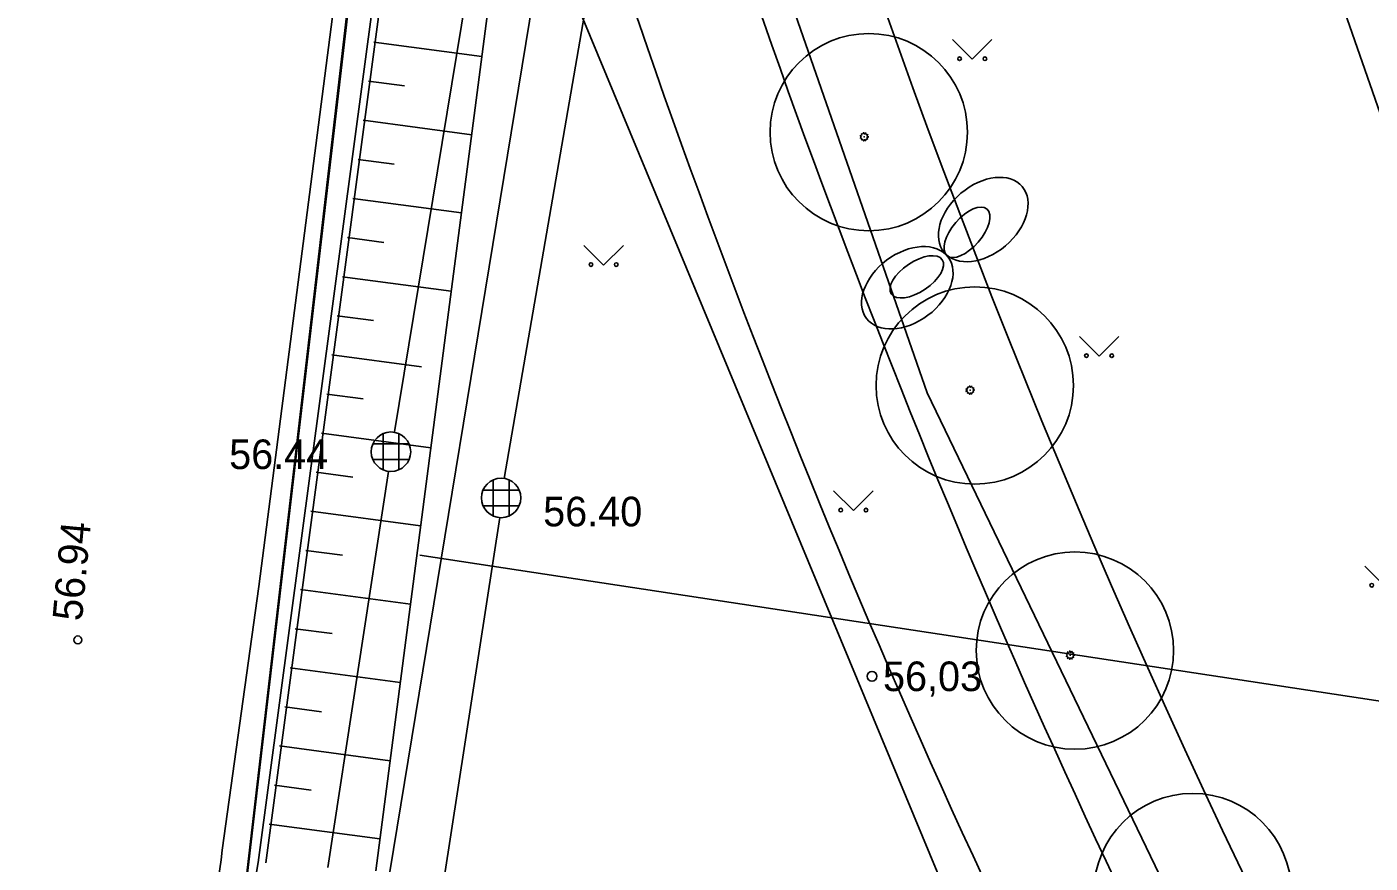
# Model space of a CAD drawing. Extents: x 9156 to 9809, y 2728 to 4000.
# Drawn here: x 9410.12 to 9444.15, y 3825.13 to 3846.32 of the extents above; entities that cross this region are included whole.
import ezdxf

# ---------------------------------------------------------------- set-up
doc = ezdxf.new("R2010")
doc.units = 0
for name, color, linetype in [('Level 12', 7, 'Continuous'), ('Level 14', 7, 'Continuous'), ('Level 17', 7, 'Continuous'), ('Level 18', 7, 'Continuous'), ('Level 41', 7, 'Continuous'), ('Level 54', 7, 'Continuous'), ('Level 56', 7, 'Continuous'), ('Level 6', 7, 'Continuous'), ('Level 7', 7, 'Continuous'), ('Level 8', 7, 'Continuous'), ('Level 9', 7, 'Continuous')]:
    doc.layers.add(name, color=color, linetype=linetype)

# ---------------------------------------------------------------- blocks, each defined once
blk = doc.blocks.new('MURU')
at = {"layer": 'Level 41'}
for p, q in [((-0.5, 0.5), (0, 0)), ((0, 0), (0.5, 0.5))]:
    blk.add_line(p, q, dxfattribs=at)
for centre in [(-0.32, 0.015), (0.32, 0.014)]:
    blk.add_circle(centre, 0.0466, dxfattribs=at)

msp = doc.modelspace()

# ---------------------------------------------------------------- linework, layer by layer
at = {"layer": 'Level 12'}
for p, q in [((9432.928, 3837.052), (9429.455, 3847.022)), ((9440.781, 3820.735), (9432.928, 3837.052))]:
    msp.add_line(p, q, dxfattribs=at)
at = {"layer": 'Level 14'}
msp.add_line((9444.967, 3842.49), (9431.28, 3881.958), dxfattribs=at)
at = {"layer": 'Level 17'}
for centre, radius, start, end in [((9631.829, 3934.713), 192.9, 187.13653, 212.29226), ((9631.829, 3934.713), 195.9, 187.89598, 211.0202), ((9639.344, 3919.894), 226, 185.96508, 207.05054), ((9639.344, 3919.894), 223, 186.63117, 207.05059)]:
    msp.add_arc(centre, radius, start, end, dxfattribs=at)
at = {"layer": 'Level 18'}
for centre, radius, start, end in [((9631.829, 3934.713), 198.9, 190.27283, 207.99609), ((9639.344, 3919.894), 220, 188.1609, 207.05049)]:
    msp.add_arc(centre, radius, start, end, dxfattribs=at)
at = {"layer": 'Level 54'}
for p, q in [((9428.052, 3915.601), (9415.976, 3825.147)), ((9427.378, 3909.376), (9416.171, 3825.133)), ((9419.432, 3836.064), (9425.772, 3874.586)), ((9429.001, 3874.205), (9422.209, 3834.878)), ((9418.905, 3845.939), (9421.645, 3845.573)), ((9418.773, 3844.948), (9419.687, 3844.826)), ((9418.64, 3843.957), (9421.387, 3843.59)), ((9418.508, 3842.966), (9419.424, 3842.843)), ((9418.375, 3841.974), (9421.128, 3841.607)), ((9418.243, 3840.983), (9419.162, 3840.861)), ((9418.111, 3839.992), (9420.87, 3839.623)), ((9417.978, 3839.001), (9418.899, 3838.878)), ((9420.75, 3838.705), (9418.955, 3824.932)), ((9417.846, 3838.01), (9420.113, 3837.707)), ((9417.713, 3837.018), (9418.636, 3836.895)), ((9417.581, 3836.027), (9420.353, 3835.657)), ((9418.884, 3835.756), (9419.8, 3835.756)), ((9419.142, 3836.014), (9419.142, 3835.098)), ((9419.542, 3836.014), (9419.542, 3835.098)), ((9417.449, 3835.036), (9418.374, 3834.912)), ((9417.739, 3825.02), (9419.277, 3835.055)), ((9418.884, 3835.356), (9419.8, 3835.356)), ((9421.932, 3834.842), (9421.932, 3833.926)), ((9422.332, 3834.842), (9422.332, 3833.926)), ((9421.674, 3834.584), (9422.59, 3834.584)), ((9417.316, 3834.045), (9420.094, 3833.674)), ((9421.674, 3834.184), (9422.59, 3834.184)), ((9420.7, 3824.806), (9422.096, 3833.885)), ((9417.184, 3833.054), (9418.111, 3832.93)), ((9417.051, 3832.062), (9419.836, 3831.691)), ((9416.919, 3831.071), (9417.848, 3830.947)), ((9416.787, 3830.08), (9419.577, 3829.707)), ((9416.654, 3829.089), (9417.585, 3828.964)), ((9416.522, 3828.098), (9419.318, 3827.724)), ((9416.389, 3827.106), (9417.323, 3826.982)), ((9416.257, 3826.115), (9419.06, 3825.741))]:
    msp.add_line(p, q, dxfattribs=at)
for points in [[(9415.997, 3832.136), (9418.853, 3854.304), (9418.853, 3854.304), (9418.027, 3862.261), (9417.976, 3870.031), (9426.142, 3917.687)], [(9419.311, 3824.906), (9430.024, 3890.161), (9433.2, 3889.656), (9434.423, 3896.884), (9431.507, 3897.561), (9431.927, 3902.125)], [(9428.218, 3901.358), (9428.633, 3899.185), (9420.75, 3838.705)], [(9520.273, 3827.766), (9490.843, 3825.804), (9472.66, 3826.338), (9457.151, 3826.873), (9448.238, 3828.654), (9420.073, 3832.93)], [(9415.037, 3825.215), (9415.063, 3825.456), (9415.997, 3832.136)], [(9430.118, 3737.47), (9419.84, 3752.661), (9416.921, 3758.115), (9414.288, 3763.295), (9411.358, 3770.89), (9409.441, 3780.316), (9410.66, 3795.64), (9415.037, 3825.215)]]:
    msp.add_lwpolyline(points, dxfattribs=at)
for centre, radius in [((9419.342, 3835.556), 0.5), ((9422.132, 3834.384), 0.5), ((9411.41, 3830.786), 0.1), ((9431.528, 3829.864), 0.125)]:
    msp.add_circle(centre, radius, dxfattribs=at)
msp.add_open_spline([(9415.976, 3825.147), (9415.093, 3819.866), (9413.578, 3808.546), (9411.641, 3794.709), (9410.924, 3784.763), (9411.76, 3776.853), (9413.792, 3771.101), (9417.009, 3763.374), (9419.226, 3759.393), (9422.553, 3753.458)], degree=3, dxfattribs=at)
at = {"layer": 'Level 56'}
for centre, radius, start, end in [((9631.829, 3934.713), 192.9, 187.13653, 212.29226), ((9631.829, 3934.713), 195.9, 187.89598, 211.0202), ((9631.829, 3934.713), 198.9, 190.27283, 207.99609), ((9639.344, 3919.894), 226, 185.96508, 207.05054), ((9639.344, 3919.894), 223, 186.63117, 207.05059), ((9639.344, 3919.894), 220, 188.1609, 207.05049)]:
    msp.add_arc(centre, radius, start, end, dxfattribs=at)
at = {"layer": 'Level 6'}
msp.add_lwpolyline([(9406.335, 3871.284), (9417.264, 3870.77), (9419.931, 3861.081), (9410.086, 3776.653), (9389.428, 3778.75), (9392.066, 3801.386), (9401.769, 3871.605)], close=True, dxfattribs=at)
msp.add_lwpolyline([(9397.586, 3777.922), (9410.086, 3776.653), (9418.608, 3850.018)], dxfattribs=at)
at = {"layer": 'Level 7'}
msp.add_line((9423.602, 3847.995), (9436.729, 3816.345), dxfattribs=at)
at = {"layer": 'Level 8'}
for centre, major_axis, ratio in [((9434.346, 3841.44), (-0.986, -0.837), 0.674652), ((9434.346, 3841.44), (-0.986, -0.837), 0.674652), ((9434.346, 3841.44), (-0.986, -0.837), 0.674652), ((9434.346, 3841.44), (-0.986, -0.837), 0.674652), ((9433.934, 3841.117), (-0.507, -0.589), 0.486914), ((9433.934, 3841.117), (-0.507, -0.589), 0.486914), ((9433.934, 3841.117), (-0.507, -0.589), 0.486914), ((9433.934, 3841.117), (-0.507, -0.589), 0.486914), ((9432.422, 3839.711), (1.034, 0.776), 0.674652), ((9432.422, 3839.711), (1.034, 0.776), 0.674652), ((9432.422, 3839.711), (1.034, 0.776), 0.674652), ((9432.422, 3839.711), (1.034, 0.776), 0.674652), ((9432.662, 3839.988), (0.646, 0.434), 0.486914), ((9432.662, 3839.988), (0.646, 0.434), 0.486914), ((9432.662, 3839.988), (0.646, 0.434), 0.486914), ((9432.662, 3839.988), (0.646, 0.434), 0.486914)]:
    msp.add_ellipse(centre, major_axis=major_axis, ratio=ratio, dxfattribs=at)
at = {"layer": 'Level 9'}
for p, q in [((9431.251, 3843.549), (9431.23, 3843.552)), ((9431.23, 3843.523), (9431.251, 3843.527)), ((9431.238, 3843.579), (9431.258, 3843.571)), ((9431.27, 3843.589), (9431.253, 3843.603)), ((9431.275, 3843.622), (9431.286, 3843.603)), ((9431.308, 3843.613), (9431.301, 3843.634)), ((9431.34, 3843.536), (9431.319, 3843.536)), ((9431.329, 3843.638), (9431.329, 3843.616)), ((9431.329, 3843.526), (9431.329, 3843.547)), ((9431.351, 3843.613), (9431.357, 3843.634)), ((9431.383, 3843.622), (9431.373, 3843.603)), ((9431.389, 3843.589), (9431.405, 3843.603)), ((9431.421, 3843.579), (9431.401, 3843.569)), ((9431.407, 3843.548), (9431.429, 3843.552)), ((9431.429, 3843.524), (9431.408, 3843.527)), ((9431.258, 3843.505), (9431.238, 3843.495)), ((9431.253, 3843.472), (9431.269, 3843.486)), ((9431.287, 3843.471), (9431.275, 3843.453)), ((9431.3, 3843.441), (9431.306, 3843.462)), ((9431.329, 3843.458), (9431.329, 3843.437)), ((9431.357, 3843.441), (9431.352, 3843.462)), ((9431.371, 3843.471), (9431.383, 3843.453)), ((9431.406, 3843.472), (9431.39, 3843.487)), ((9431.401, 3843.505), (9431.421, 3843.497)), ((9433.936, 3837.129), (9433.915, 3837.132)), ((9433.915, 3837.104), (9433.936, 3837.107)), ((9433.923, 3837.16), (9433.943, 3837.152)), ((9433.943, 3837.085), (9433.923, 3837.076)), ((9433.938, 3837.052), (9433.954, 3837.067)), ((9433.955, 3837.17), (9433.939, 3837.184)), ((9433.96, 3837.202), (9433.971, 3837.184)), ((9433.993, 3837.194), (9433.986, 3837.214)), ((9434.025, 3837.117), (9434.004, 3837.117)), ((9434.014, 3837.218), (9434.014, 3837.197)), ((9434.015, 3837.106), (9434.015, 3837.127)), ((9434.036, 3837.194), (9434.042, 3837.215)), ((9434.068, 3837.203), (9434.058, 3837.184)), ((9434.074, 3837.17), (9434.09, 3837.184)), ((9434.091, 3837.053), (9434.075, 3837.067)), ((9434.106, 3837.16), (9434.086, 3837.15)), ((9434.087, 3837.086), (9434.106, 3837.077)), ((9434.093, 3837.129), (9434.114, 3837.133)), ((9434.114, 3837.104), (9434.093, 3837.108)), ((9433.972, 3837.051), (9433.96, 3837.033)), ((9433.986, 3837.022), (9433.992, 3837.042)), ((9434.014, 3837.039), (9434.014, 3837.017)), ((9434.042, 3837.021), (9434.037, 3837.042)), ((9434.057, 3837.051), (9434.069, 3837.033)), ((9436.472, 3830.411), (9436.451, 3830.414)), ((9436.451, 3830.386), (9436.472, 3830.389)), ((9436.459, 3830.442), (9436.479, 3830.434)), ((9436.479, 3830.367), (9436.459, 3830.358)), ((9436.491, 3830.452), (9436.474, 3830.466)), ((9436.474, 3830.334), (9436.49, 3830.349)), ((9436.496, 3830.484), (9436.507, 3830.466)), ((9436.508, 3830.333), (9436.496, 3830.315)), ((9436.529, 3830.476), (9436.522, 3830.496)), ((9436.522, 3830.303), (9436.527, 3830.324)), ((9436.561, 3830.399), (9436.54, 3830.399)), ((9436.55, 3830.5), (9436.55, 3830.479)), ((9436.55, 3830.321), (9436.55, 3830.299)), ((9436.551, 3830.388), (9436.551, 3830.409)), ((9436.572, 3830.476), (9436.578, 3830.497)), ((9436.578, 3830.303), (9436.573, 3830.324)), ((9436.593, 3830.333), (9436.605, 3830.315)), ((9436.604, 3830.485), (9436.594, 3830.466)), ((9436.61, 3830.452), (9436.626, 3830.466)), ((9436.627, 3830.335), (9436.611, 3830.349)), ((9436.642, 3830.442), (9436.622, 3830.432)), ((9436.623, 3830.368), (9436.642, 3830.359)), ((9436.629, 3830.411), (9436.65, 3830.415)), ((9436.65, 3830.386), (9436.629, 3830.39))]:
    msp.add_line(p, q, dxfattribs=at)
for centre in [(9431.447, 3843.654), (9434.132, 3837.234), (9436.668, 3830.516), (9439.651, 3824.395)]:
    msp.add_circle(centre, 2.5, dxfattribs=at)
for centre, radius, start, end in [((9431.329, 3843.537), 0.101, 155.3123, 171.7042), ((9431.329, 3843.537), 0.0788, 171.5431, 187.6203), ((9431.329, 3843.537), 0.101, 122.8434, 139.0222), ((9431.329, 3843.537), 0.0788, 138.6432, 154.5795), ((9431.329, 3843.537), 0.0788, 105.9559, 123.0564), ((9431.329, 3843.537), 0.101, 90.0356, 106.342), ((9431.329, 3843.537), 0.0788, 74.31, 90.043), ((9431.329, 3843.537), 0.101, 57.6108, 74.1981), ((9431.329, 3843.537), 0.0788, 41.2062, 56.7795), ((9431.329, 3843.537), 0.0788, 8.0619, 24.0332), ((9431.329, 3843.537), 0.0788, 336.0557, 352.7558), ((9431.329, 3843.537), 0.101, 24.5394, 40.9852), ((9431.329, 3843.537), 0.101, 352.27, 8.583), ((9431.329, 3843.537), 0.101, 187.9671, 204.8625), ((9431.329, 3843.537), 0.101, 220.7122, 237.1166), ((9431.329, 3843.537), 0.0788, 204.4529, 220.4774), ((9431.329, 3843.537), 0.0788, 237.451, 253.0843), ((9431.329, 3843.537), 0.101, 253.2952, 269.5718), ((9431.329, 3843.537), 0.0788, 269.9461, 286.3473), ((9431.329, 3843.537), 0.101, 285.972, 302.5562), ((9431.329, 3843.537), 0.0788, 302.254, 320.086), ((9431.329, 3843.537), 0.101, 319.7777, 336.0738), ((9434.014, 3837.118), 0.101, 155.3123, 171.7042), ((9434.014, 3837.118), 0.101, 187.9671, 204.8625), ((9434.014, 3837.118), 0.0788, 171.5431, 187.6203), ((9434.014, 3837.118), 0.101, 122.8434, 139.0222), ((9434.014, 3837.118), 0.0788, 138.6432, 154.5795), ((9434.014, 3837.118), 0.0788, 204.4529, 220.4774), ((9434.014, 3837.118), 0.0788, 105.9559, 123.0564), ((9434.014, 3837.118), 0.101, 90.0356, 106.342), ((9434.014, 3837.118), 0.0788, 74.31, 90.043), ((9434.014, 3837.118), 0.101, 57.6108, 74.1981), ((9434.014, 3837.118), 0.0788, 302.254, 320.086), ((9434.014, 3837.118), 0.0788, 41.2062, 56.7795), ((9434.014, 3837.118), 0.0788, 8.0619, 24.0332), ((9434.014, 3837.118), 0.0788, 336.0557, 352.7558), ((9434.014, 3837.118), 0.101, 24.5394, 40.9852), ((9434.014, 3837.118), 0.101, 319.7777, 336.0738), ((9434.014, 3837.118), 0.101, 352.27, 8.583), ((9434.014, 3837.118), 0.101, 220.7122, 237.1166), ((9434.014, 3837.118), 0.0788, 237.451, 253.0843), ((9434.014, 3837.118), 0.101, 253.2952, 269.5718), ((9434.014, 3837.118), 0.0788, 269.9461, 286.3473), ((9434.014, 3837.118), 0.101, 285.972, 302.5562), ((9436.55, 3830.4), 0.101, 155.3123, 171.7042), ((9436.55, 3830.4), 0.101, 187.9671, 204.8625), ((9436.55, 3830.4), 0.0788, 171.5431, 187.6203), ((9436.55, 3830.4), 0.101, 220.7122, 237.1166), ((9436.55, 3830.4), 0.101, 122.8434, 139.0222), ((9436.55, 3830.4), 0.0788, 138.6432, 154.5795), ((9436.55, 3830.4), 0.0788, 204.4529, 220.4774), ((9436.55, 3830.4), 0.0788, 105.9559, 123.0564), ((9436.55, 3830.4), 0.0788, 237.451, 253.0843), ((9436.55, 3830.4), 0.101, 90.0356, 106.342), ((9436.55, 3830.4), 0.101, 253.2952, 269.5718), ((9436.55, 3830.4), 0.0788, 74.31, 90.043), ((9436.55, 3830.4), 0.0788, 269.9461, 286.3473), ((9436.55, 3830.4), 0.101, 57.6108, 74.1981), ((9436.55, 3830.4), 0.101, 285.972, 302.5562), ((9436.55, 3830.4), 0.0788, 302.254, 320.086), ((9436.55, 3830.4), 0.0788, 41.2062, 56.7795), ((9436.55, 3830.4), 0.0788, 8.0619, 24.0332), ((9436.55, 3830.4), 0.0788, 336.0557, 352.7558), ((9436.55, 3830.4), 0.101, 24.5394, 40.9852), ((9436.55, 3830.4), 0.101, 319.7777, 336.0738), ((9436.55, 3830.4), 0.101, 352.27, 8.583)]:
    msp.add_arc(centre, radius, start, end, dxfattribs=at)

# ---------------------------------------------------------------- block references
at = {"layer": 'Level 54'}
for p in [(9434.067, 3845.502), (9424.729, 3840.284), (9437.28, 3837.976), (9431.055, 3834.062), (9444.509, 3832.156)]:
    msp.add_blockref('MURU', p, dxfattribs=at)

# ---------------------------------------------------------------- texts
for s, p in [('56.44', (9415.243, 3835.116)), ('56.40', (9423.197, 3833.665)), (' 56,03', (9431.528, 3829.489))]:
    msp.add_text(s, height=0.75, dxfattribs=at).set_placement(p)
msp.add_text('56.94', height=0.75, rotation=84.7745, dxfattribs=at).set_placement((9411.512, 3831.247))

doc.saveas('drawing.dxf')
